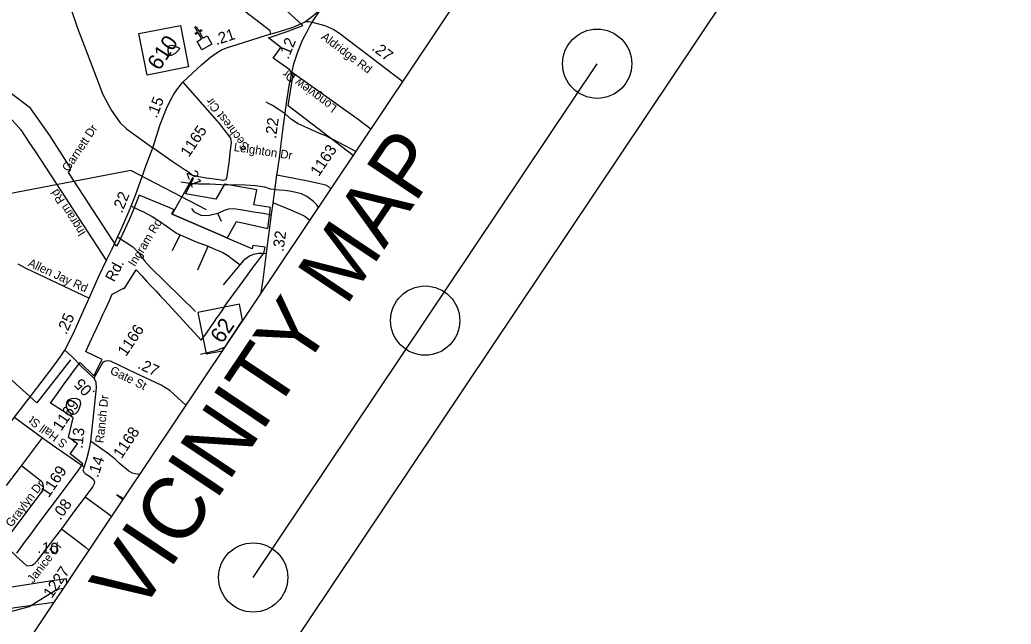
# Model space of a CAD drawing. Extents: x 1715610 to 1720914, y 798298 to 802505.
# Drawn here: x 1716054.7 to 1716295.1, y 799408.1 to 799554.8 of the extents above; entities that cross this region are included whole.
import ezdxf

# ---------------------------------------------------------------- set-up
doc = ezdxf.new("R2010")
doc.units = 0
doc.layers.add('Default', color=7, linetype='Continuous')
doc.layers.add('Prop DSN Text', color=7, linetype='Continuous')

msp = doc.modelspace()

# ---------------------------------------------------------------- linework, layer by layer
at = {"layer": 'Default'}
for p, q in [((1716103.59, 799505.81), (1716102.74, 799507.81)), ((1716091.71, 799498.76), (1716093.58, 799502.6)), ((1716097.85, 799494.11), (1716100.39, 799499.82)), ((1716104.05, 799490.45), (1716108.09, 799495.35)), ((1716103.82, 799474.49), (1716108.72, 799481.82)), ((1716053.45, 799458.31), (1716060.2, 799453.38)), ((1716055.08, 799446.56), (1716060.2, 799453.38)), ((1716051.49, 799441.8), (1716055.08, 799446.56))]:
    msp.add_line(p, q, dxfattribs=at)
for points in [[(1716135.5, 799521.82), (1716119.76, 799533.88), (1716120.92, 799540.98), (1716120.2, 799542.66), (1716116.17, 799545.47), (1716118, 799548.07), (1716114.99, 799550.42), (1716119.52, 799551.92), (1716123.32, 799553.42), (1716119.54, 799556.9), (1716117.06, 799558.69), (1716109.93, 799563.38), (1716087.19, 799580.88), (1716088.88, 799582.87), (1716060.14, 799604.73), (1716058.21, 799606.69), (1716067.68, 799613.64), (1716103.5, 799614.09), (1716121.16, 799634.15)], [(1716135.5, 799521.82), (1716119.76, 799533.88), (1716120.92, 799540.98), (1716120.2, 799542.66), (1716116.17, 799545.47), (1716118, 799548.07), (1716114.99, 799550.42), (1716119.52, 799551.92), (1716123.32, 799553.42), (1716119.54, 799556.9), (1716117.06, 799558.69), (1716109.93, 799563.38), (1716087.19, 799580.88), (1716088.88, 799582.87), (1716060.14, 799604.73), (1716058.21, 799606.69), (1716067.68, 799613.64), (1716103.5, 799614.09), (1716121.16, 799634.15)], [(1716125.61, 799554.2), (1716127.74, 799557.46), (1716130.02, 799560.94), (1716133.76, 799566.61), (1716135.23, 799568.99), (1716137.96, 799572.93), (1716140.85, 799577.4), (1716143.14, 799580.98), (1716145.26, 799584.22), (1716147.25, 799587.27), (1716150.73, 799592.47), (1716152.2, 799594.66), (1716154.43, 799597.46)], [(1716054.67, 799586.59), (1716055.43, 799581.78), (1716055.76, 799579.54), (1716056.36, 799577.31), (1716056.94, 799575.95), (1716057.52, 799575.11), (1716058.34, 799573.98), (1716060.42, 799571.98), (1716062.05, 799570.57), (1716062.97, 799569.32), (1716064.06, 799567.64), (1716064.82, 799565.56), (1716066.06, 799561), (1716067.06, 799557.48), (1716068.7, 799552.78), (1716071.13, 799546.44), (1716074.79, 799536.65), (1716076.89, 799532.76), (1716079.06, 799529.74), (1716080.59, 799528.32), (1716086.92, 799523.74)], [(1716115.47, 799551.44), (1716115.41, 799552.14), (1716105.72, 799559.54)], [(1716123.74, 799554.22), (1716125.66, 799555.67), (1716126.78, 799556.64), (1716127.74, 799557.46)], [(1716094.25, 799539.65), (1716098.86, 799543.96), (1716100.93, 799545.68), (1716102.59, 799546.87), (1716103.63, 799547.45), (1716105.04, 799548.03), (1716107.4, 799548.81), (1716114.5, 799551.03), (1716117.71, 799551.97), (1716120.96, 799552.99), (1716123.74, 799554.22), (1716124, 799554.33), (1716124.27, 799554.37), (1716124.77, 799554.39), (1716125.61, 799554.2)], [(1716117.04, 799517.05), (1716117.63, 799521.18), (1716117.97, 799524.04), (1716118.47, 799527.9), (1716119.37, 799534.56), (1716120.01, 799538.72), (1716120.71, 799542.27), (1716121.17, 799544.13), (1716122.1, 799547.03), (1716123.1, 799549.47), (1716123.68, 799550.68), (1716124.36, 799551.95), (1716124.94, 799553.08), (1716125.61, 799554.2)], [(1716125.61, 799554.2), (1716128.67, 799553.38), (1716130.84, 799552.45), (1716132.23, 799551.51), (1716134.04, 799550.15), (1716139.01, 799546.36), (1716147.56, 799539.84)], [(1716091, 799548.54), (1716091.62, 799548.59), (1716092.54, 799548.32), (1716093.43, 799547.93), (1716093.23, 799547.49), (1716092.41, 799546.67), (1716091.92, 799546.33), (1716091.39, 799546.11), (1716090.9, 799546.08), (1716090.73, 799546.29), (1716090.74, 799546.92), (1716090.66, 799547.66), (1716091, 799548.54)], [(1716091, 799548.54), (1716091.62, 799548.59), (1716092.54, 799548.32), (1716093.43, 799547.93), (1716093.23, 799547.49), (1716092.41, 799546.67), (1716091.92, 799546.33), (1716091.39, 799546.11), (1716090.9, 799546.08), (1716090.73, 799546.29), (1716090.66, 799547.66), (1716091, 799548.54)], [(1716120.73, 799542.1), (1716136.76, 799530.64), (1716139.85, 799528.32)], [(1716091.62, 799507.59), (1716091.52, 799507.63), (1716091.53, 799507.66), (1716092.11, 799508.7), (1716091.11, 799509.12), (1716083.67, 799512.22), (1716082.85, 799510.24), (1716082.07, 799508.36), (1716081.19, 799506.26), (1716079.61, 799502.79), (1716078.66, 799500.69), (1716078.11, 799499.86), (1716077.27, 799501.25), (1716066.5, 799517.71), (1716066.94, 799518.47), (1716066.86, 799519.04), (1716066.68, 799519.33), (1716061.96, 799526.72), (1716057.25, 799533.34), (1716050.04, 799538.83)], [(1716091.62, 799507.59), (1716091.52, 799507.63), (1716091.53, 799507.66), (1716092.11, 799508.7), (1716091.11, 799509.12), (1716083.67, 799512.22), (1716082.85, 799510.24), (1716082.07, 799508.36), (1716081.19, 799506.26), (1716079.61, 799502.79), (1716078.66, 799500.69), (1716078.11, 799499.86), (1716077.27, 799501.25), (1716066.5, 799517.71), (1716066.94, 799518.47), (1716066.86, 799519.04), (1716066.68, 799519.33), (1716061.96, 799526.72), (1716057.25, 799533.34), (1716050.04, 799538.83)], [(1716086.92, 799523.74), (1716088.76, 799529.38), (1716090.46, 799533.63), (1716091.61, 799535.97), (1716092.07, 799536.71), (1716093.03, 799538.14), (1716094.25, 799539.65)], [(1716094.25, 799539.65), (1716099.02, 799534.22), (1716102.52, 799530.19), (1716102.78, 799529.9), (1716105.82, 799526.08), (1716105.95, 799524.94), (1716105.64, 799522.56), (1716105.57, 799521.51), (1716105.36, 799520.09)], [(1716136.17, 799522.83), (1716133.56, 799524.21), (1716130.37, 799525.86), (1716128.91, 799526.59), (1716127.36, 799527.18), (1716125.07, 799528.22), (1716122.22, 799529.53), (1716120.62, 799530.57), (1716119.01, 799531.99), (1716117.08, 799533.25), (1716115.94, 799533.98), (1716114.97, 799534.48), (1716114.41, 799534.76)], [(1716051.41, 799531.58), (1716051.64, 799531.43), (1716052.86, 799530.43), (1716053.76, 799529.45), (1716054.94, 799528.1), (1716056.87, 799525.11), (1716058.48, 799522.74), (1716064.58, 799513.45), (1716075.73, 799496.25)], [(1716065.57, 799474.64), (1716067.02, 799477.41), (1716067.99, 799479.43), (1716070.31, 799484.58), (1716071.48, 799487.2), (1716073.97, 799492.71), (1716075.75, 799496.46), (1716077.08, 799499.19), (1716078.38, 799502.06), (1716079.49, 799504.48), (1716081.52, 799509.15), (1716082.76, 799512.24), (1716084.27, 799516.53), (1716085.33, 799519.48), (1716086.92, 799523.74)], [(1716105.36, 799520.09), (1716104.85, 799516.32), (1716104.62, 799515.91), (1716104.08, 799515.8), (1716102.51, 799516), (1716099.99, 799516.36), (1716098.09, 799516.71), (1716096.71, 799517.03), (1716096.17, 799517.35), (1716095.64, 799517.75), (1716095.18, 799518.03), (1716094.8, 799518.27), (1716091.84, 799520.25), (1716086.92, 799523.74)], [(1716099.95, 799508.66), (1716081.61, 799518.23), (1716051.68, 799512.5)], [(1716094.87, 799512.57), (1716096.85, 799516.27), (1716096.54, 799516.41), (1716094.2, 799512.22), (1716093.02, 799510.11), (1716091.62, 799507.59)], [(1716094.87, 799512.57), (1716096.85, 799516.27), (1716096.54, 799516.41), (1716094.2, 799512.22), (1716093.02, 799510.11), (1716091.62, 799507.59)], [(1716113.26, 799488.6), (1716113.69, 799491.66), (1716114.59, 799498.79), (1716115.76, 799507.57), (1716116.14, 799510.32), (1716117.04, 799517.05)], [(1716130.13, 799513.8), (1716129.62, 799514.26), (1716128.88, 799514.66), (1716127.49, 799514.98), (1716124.92, 799515.5), (1716121.22, 799516.27), (1716117.04, 799517.05)], [(1716127.09, 799509.26), (1716126.71, 799509.86), (1716125.93, 799510.66), (1716124.32, 799511.92), (1716122.97, 799512.57), (1716120.55, 799513.12), (1716118.98, 799513.36), (1716117.55, 799513.43), (1716115.47, 799513.7), (1716114.13, 799514.13), (1716111.82, 799514.45), (1716109.31, 799514.64), (1716106.89, 799514.71), (1716104.86, 799514.67), (1716100.78, 799514.87), (1716099.02, 799514.92), (1716098.05, 799514.89), (1716096.63, 799514.97), (1716095.9, 799515.05), (1716094.8, 799515.22), (1716093.76, 799515.4)], [(1716104.98, 799501.83), (1716107.23, 799505.8), (1716114.81, 799504.13), (1716115.45, 799509.27), (1716111.48, 799509.9), (1716112.15, 799513.55), (1716104.34, 799514.93), (1716102.19, 799511.29), (1716094.87, 799512.57)], [(1716104.98, 799501.83), (1716107.23, 799505.8), (1716114.81, 799504.13), (1716115.45, 799509.27), (1716111.48, 799509.9), (1716112.15, 799513.55), (1716104.34, 799514.93), (1716102.19, 799511.29), (1716094.87, 799512.57)], [(1716081.77, 799509.59), (1716083.52, 799508.68), (1716084.71, 799508.15), (1716085.76, 799507.64), (1716086.82, 799507.04), (1716088.78, 799505.75), (1716091.57, 799503.81), (1716092.69, 799503.03), (1716093.58, 799502.6)], [(1716116.18, 799510.36), (1716120.57, 799508.57), (1716123.64, 799507.19), (1716124.13, 799506.86), (1716125, 799506.14)], [(1716091.62, 799507.59), (1716095.02, 799506.12), (1716100.27, 799503.86), (1716103.99, 799502.26), (1716104.88, 799501.88), (1716104.98, 799501.83)], [(1716091.62, 799507.59), (1716095.02, 799506.12), (1716100.27, 799503.86), (1716103.99, 799502.26), (1716104.88, 799501.88), (1716104.98, 799501.83)], [(1716104.98, 799501.83), (1716104.88, 799501.88), (1716103.99, 799502.26), (1716100.27, 799503.86), (1716095.02, 799506.12), (1716091.62, 799507.59)], [(1716104.98, 799501.83), (1716104.88, 799501.88), (1716103.99, 799502.26), (1716100.27, 799503.86), (1716095.02, 799506.12), (1716091.62, 799507.59)], [(1716102.74, 799507.81), (1716100.34, 799507.2), (1716098.7, 799507.31), (1716097.06, 799508.11), (1716096.42, 799508.99)], [(1716115.8, 799507.39), (1716114.63, 799507.62), (1716113.23, 799507.84), (1716111.45, 799508.13), (1716110.03, 799508.37), (1716108.69, 799508.6), (1716106.5, 799508.91), (1716105.3, 799508.81), (1716104.23, 799508.53), (1716102.74, 799507.81)], [(1716053.94, 799425.36), (1716055.85, 799427.91), (1716057.41, 799430.01), (1716058.68, 799431.71), (1716060.55, 799434.22), (1716062.07, 799436.26), (1716063.59, 799438.3), (1716066.9, 799442.74), (1716068.79, 799445.29), (1716069.36, 799446.07), (1716070, 799447.02), (1716066.86, 799449.44), (1716068.64, 799451.87), (1716067.75, 799452.53), (1716066.9, 799453.14), (1716066.47, 799453.46), (1716067.64, 799458.21), (1716067.31, 799458.43), (1716066.89, 799458.7), (1716064.97, 799459.95), (1716062.12, 799461.78), (1716063.59, 799463.81), (1716065.71, 799466.74), (1716066.98, 799468.48), (1716067.5, 799469.21), (1716068.76, 799470.92), (1716069.36, 799471.6), (1716072.67, 799468.39), (1716074.65, 799472.36), (1716070.76, 799474.22), (1716070.69, 799474.26), (1716071.6, 799476.24), (1716072.54, 799478.3), (1716073.9, 799481.27), (1716074.33, 799482.17), (1716074.82, 799483.25), (1716075.43, 799484.57), (1716075.92, 799485.61), (1716076.41, 799486.68), (1716077.12, 799488.2), (1716079.88, 799489.68), (1716079.99, 799489.47), (1716082.89, 799494.13), (1716084.27, 799492.64), (1716085.43, 799491.38), (1716086.62, 799490.09), (1716087.72, 799488.9), (1716088.81, 799487.72), (1716089.82, 799486.63), (1716098.7, 799477.01), (1716099.52, 799478.17), (1716099.94, 799478.77), (1716101.88, 799481.53), (1716102.51, 799482.43), (1716102.94, 799483.05), (1716103.98, 799484.56), (1716104.59, 799485.5), (1716104.99, 799486.06), (1716107.49, 799489.5), (1716109.66, 799492.5), (1716111.27, 799494.72), (1716111.94, 799495.6), (1716112.69, 799496.57), (1716113.63, 799497.8), (1716113.9, 799498.14), (1716114.16, 799499.63), (1716111.18, 799500.01), (1716111.05, 799499.22), (1716104.98, 799501.83)], [(1716053.94, 799425.36), (1716055.85, 799427.91), (1716057.41, 799430.01), (1716058.68, 799431.71), (1716060.55, 799434.22), (1716062.07, 799436.26), (1716063.59, 799438.3), (1716066.9, 799442.74), (1716068.79, 799445.29), (1716069.36, 799446.07), (1716070, 799447.02), (1716066.86, 799449.44), (1716068.64, 799451.87), (1716067.75, 799452.53), (1716066.9, 799453.14), (1716066.47, 799453.46), (1716067.64, 799458.21), (1716067.31, 799458.43), (1716066.89, 799458.7), (1716064.97, 799459.95), (1716062.12, 799461.78), (1716063.59, 799463.81), (1716065.71, 799466.74), (1716066.98, 799468.48), (1716067.5, 799469.21), (1716068.76, 799470.92), (1716069.36, 799471.6), (1716072.67, 799468.39), (1716074.65, 799472.36), (1716070.76, 799474.22), (1716070.69, 799474.26), (1716071.6, 799476.24), (1716072.54, 799478.3), (1716073.9, 799481.27), (1716074.33, 799482.17), (1716074.82, 799483.25), (1716075.43, 799484.57), (1716075.92, 799485.61), (1716076.41, 799486.68), (1716077.12, 799488.2), (1716079.88, 799489.68), (1716079.99, 799489.47), (1716082.89, 799494.13), (1716084.27, 799492.64), (1716085.43, 799491.38), (1716086.62, 799490.09), (1716087.72, 799488.9), (1716088.81, 799487.72), (1716089.82, 799486.63), (1716098.7, 799477.01), (1716099.52, 799478.17), (1716099.94, 799478.77), (1716101.88, 799481.53), (1716102.51, 799482.43), (1716102.94, 799483.05), (1716103.98, 799484.56), (1716104.59, 799485.5), (1716104.99, 799486.06), (1716107.49, 799489.5), (1716109.66, 799492.5), (1716111.27, 799494.72), (1716111.94, 799495.6), (1716112.69, 799496.57), (1716113.63, 799497.8), (1716113.9, 799498.14), (1716114.16, 799499.63), (1716111.18, 799500.01), (1716111.05, 799499.22), (1716104.98, 799501.83)], [(1716078.4, 799502.08), (1716082.12, 799499.65), (1716083.22, 799498.58), (1716084.91, 799496.25), (1716086.29, 799494.73), (1716097.31, 799484.03)], [(1716093.58, 799502.6), (1716097.46, 799500.89), (1716100.39, 799499.82)], [(1716100.39, 799499.82), (1716101.62, 799499.31), (1716102.76, 799498.82), (1716103.89, 799498.34), (1716105.14, 799497.61), (1716106.21, 799496.81), (1716108.09, 799495.35)], [(1716108.09, 799495.35), (1716109, 799496.4), (1716109.3, 799496.68), (1716109.53, 799496.89), (1716109.85, 799497.12), (1716110.19, 799497.35), (1716110.54, 799497.55), (1716111, 799497.76), (1716111.39, 799497.89), (1716111.78, 799498.01), (1716112.17, 799498.1), (1716112.68, 799498.16), (1716113.08, 799498.18), (1716113.49, 799498.17), (1716114.6, 799498.04)], [(1716054.21, 799495.53), (1716056.16, 799494.52), (1716071.51, 799487.21)], [(1716108.72, 799481.82), (1716107.95, 799485.75), (1716097.9, 799483.76), (1716099.89, 799473.71), (1716103.82, 799474.49)], [(1716023.72, 799419.39), (1716026.89, 799423.57), (1716029.74, 799427.26), (1716032.22, 799430.44), (1716036.41, 799435.99), (1716038.67, 799439.03), (1716041.25, 799442.43), (1716044.69, 799447.05), (1716047.5, 799450.64), (1716049.59, 799453.33), (1716053.37, 799458.34), (1716057.77, 799464.03), (1716060.13, 799467.06), (1716062.42, 799470.15), (1716064.65, 799473.19), (1716065.57, 799474.64)], [(1716065.57, 799474.64), (1716066.3, 799473.94), (1716067.48, 799472.92), (1716069.84, 799470.46), (1716072.65, 799467.8)], [(1716104.33, 799475.26), (1716104.1, 799475.14), (1716102.26, 799474.45), (1716098.52, 799473.53)], [(1716066.98, 799472.26), (1716058.84, 799461.87), (1716047.55, 799471.96)], [(1716094.96, 799461.25), (1716091.08, 799464.81), (1716088.93, 799466.15), (1716086.41, 799467.31), (1716082.76, 799469.04), (1716076.7, 799471.93), (1716076.03, 799472.04), (1716075.25, 799471.88), (1716074.75, 799471.54), (1716074.36, 799470.85), (1716072.65, 799467.8)], [(1716072.65, 799467.8), (1716072.84, 799467.58), (1716073.15, 799466.82), (1716073.22, 799465.5), (1716072.65, 799460.09), (1716071.87, 799452.54)], [(1716069.28, 799462.51), (1716068.34, 799462.9), (1716067.22, 799462.82), (1716066.48, 799462.58), (1716066.07, 799462.13), (1716065.93, 799461.38), (1716066.01, 799460.58), (1716066.57, 799459.63), (1716067.27, 799459.1), (1716067.71, 799459.06), (1716068.24, 799459.22), (1716068.95, 799459.95), (1716069.25, 799460.85), (1716069.45, 799461.61), (1716069.43, 799462.05), (1716069.28, 799462.51)], [(1716069.28, 799462.51), (1716068.34, 799462.9), (1716067.22, 799462.82), (1716066.48, 799462.58), (1716066.07, 799462.13), (1716065.93, 799461.38), (1716066.01, 799460.58), (1716066.57, 799459.63), (1716067.27, 799459.1), (1716067.71, 799459.06), (1716068.24, 799459.22), (1716068.95, 799459.95), (1716069.25, 799460.85), (1716069.45, 799461.61), (1716069.43, 799462.05), (1716069.28, 799462.51)], [(1716060.2, 799453.38), (1716063.26, 799451.19), (1716070.26, 799446.33)], [(1716071.87, 799452.54), (1716071.64, 799451.6), (1716071.31, 799450.04), (1716070.87, 799448.17), (1716070.18, 799446.05), (1716070.01, 799445.61), (1716070.16, 799445.2), (1716070.25, 799445.02), (1716070.57, 799444.71), (1716071.84, 799443.89), (1716072.48, 799443.32), (1716072.76, 799442.78), (1716072.72, 799442.2), (1716072.36, 799441.56), (1716070.55, 799439.01)], [(1716083.73, 799444.48), (1716082.78, 799444.57), (1716081.98, 799444.79), (1716081.12, 799445.22), (1716078.82, 799447.17), (1716077.81, 799448.2), (1716075.92, 799449.65), (1716071.87, 799452.54)], [(1716050.64, 799427.74), (1716060.23, 799440.56), (1716060.4, 799441.07), (1716060.44, 799441.46), (1716060.38, 799441.99), (1716060.15, 799442.47), (1716059.91, 799442.78), (1716055.08, 799446.56)], [(1716079.8, 799438.61), (1716078.24, 799439.47), (1716079.65, 799438.38)], [(1716079.8, 799438.61), (1716078.24, 799439.47), (1716079.65, 799438.38)], [(1716070.55, 799439.01), (1716067.94, 799435.66), (1716064.79, 799431.22)], [(1716070.55, 799439.01), (1716075.64, 799435.33), (1716076.95, 799434.35)], [(1716064.79, 799431.22), (1716063.08, 799429.08), (1716060.17, 799425.3), (1716058.82, 799423.41), (1716058.15, 799422.7), (1716057.72, 799422.33), (1716057.45, 799422.27)], [(1716064.79, 799431.22), (1716070.52, 799426.9), (1716071.43, 799426.1)], [(1716066.09, 799418.12), (1716066.04, 799419.13), (1716061.96, 799418.53), (1716050.15, 799416.73), (1716045.18, 799421.02), (1716036.77, 799428.3), (1716034, 799424.6), (1716029.92, 799419.28), (1716027.99, 799416.77)], [(1716066.09, 799418.12), (1716066.04, 799419.13), (1716061.96, 799418.53), (1716050.15, 799416.73), (1716045.18, 799421.02), (1716036.77, 799428.3), (1716034, 799424.6), (1716029.92, 799419.28), (1716027.99, 799416.77)], [(1716050.64, 799427.74), (1716053.64, 799424.8), (1716056.38, 799422.25), (1716057.7, 799422.46)], [(1716062.92, 799413.39), (1716051.75, 799411.85), (1716048.28, 799412.09), (1716046.02, 799414.13), (1716039.22, 799419.49)], [(1716065.19, 799416.77), (1716063.71, 799416.54), (1716056.96, 799412.37), (1716050.23, 799410.59), (1716029.64, 799389.75)]]:
    msp.add_lwpolyline(points, dxfattribs=at)
for points in [[(1716085.57, 799541.38), (1716083.58, 799551.43), (1716093.62, 799553.42), (1716095.61, 799543.37)], [(1716097.68, 799549.53), (1716098.76, 799550.13), (1716097.96, 799551.58), (1716097.35, 799551.24), (1716097.18, 799551.54), (1716097.79, 799551.88), (1716097.16, 799553.02), (1716097.46, 799553.19), (1716098.1, 799552.05), (1716098.71, 799552.39), (1716098.87, 799552.08), (1716098.26, 799551.74), (1716099.07, 799550.29), (1716100.16, 799550.9), (1716101.28, 799548.87), (1716098.8, 799547.5)]]:
    msp.add_lwpolyline(points, close=True, dxfattribs=at)
at = {"layer": 'Prop DSN Text'}
msp.add_line((1716111.28, 799419.46), (1716194.72, 799544.12), dxfattribs=at)
for points in [[(1715972.32, 799278.02), (1716250.51, 799693.66), (1715888.23, 799936.14), (1715610.03, 799520.5)], [(1715972.32, 799278.02), (1716250.51, 799693.66), (1716295.13, 799663.8), (1716016.93, 799248.16)]]:
    msp.add_lwpolyline(points, close=True, dxfattribs=at)
for centre in [(1716194.72, 799544.12), (1716153, 799481.79), (1716111.28, 799419.46)]:
    msp.add_circle(centre, 8.4, dxfattribs=at)

# ---------------------------------------------------------------- texts
at = {"layer": 'Default'}
for s, height, rotation, p in [('.21', 2.719, 18.2368, (1716102.37, 799548.58)), ('610', 3.806, 56.2051, (1716088.51, 799542.27)), ('.12', 2.719, 67.5952, (1716119.81, 799545.06)), ('Aldridge Rd', 2.0663, 323.0638, (1716127.59, 799550.29)), ('.27', 2.719, 322.5492, (1716139.87, 799547.6)), ('Longview Dr', 2.0663, 143.682, (1716131.75, 799533.73)), ('.15', 2.719, 68.2798, (1716087.85, 799530.75)), ('Sechrest Cir', 2.0663, 126.9771, (1716110.42, 799523.98)), ('.22', 2.719, 82.2733, (1716116.82, 799525.84)), ('Garnett Dr', 2.066, 56.2051, (1716066.49, 799517.77)), ('1165', 2.719, 56.2051, (1716095.68, 799521.26)), ('Leighton Dr', 2.0663, 351.4609, (1716106.49, 799522.96)), ('1163', 2.719, 56.2051, (1716127.2, 799516.6)), ('.21', 2.719, 290.5699, (1716094.67, 799518.61)), ('Ingram Rd', 2.066, 122.6768, (1716070.77, 799503.1)), ('.22', 2.719, 68.2476, (1716079.48, 799507.7)), ('Ingram Rd', 2.066, 58.5915, (1716082.58, 799494.73)), ('.32', 2.719, 82.4242, (1716118.65, 799498.38)), ('Allen Jay Rd', 2.0663, 335.3224, (1716056.49, 799495.08)), ('Rd.', 2.61, 62.7185, (1716077.57, 799491.01)), ('.25', 2.719, 65.7217, (1716065.95, 799478.21)), ('1166', 2.719, 56.2051, (1716080.45, 799472.95)), ('62', 3.806, 56.2051, (1716103.77, 799476.01)), ('Gate St', 2.066, 333.7816, (1716076.38, 799469.01)), ('.27', 2.719, 334.4183, (1716083.05, 799470.33)), ('.05', 2.719, 134.465, (1716073.1, 799464.4)), ('Ranch Dr', 2.066, 83.9755, (1716075, 799451.99)), ('1169', 2.719, 56.2051, (1716064.71, 799454.8)), ('S Hall St', 2.066, 143.5924, (1716066.41, 799452.35)), ('.13', 2.719, 84.079, (1716069.86, 799450.64)), ('1168', 2.719, 56.2051, (1716079.37, 799448.13)), ('.14', 2.719, 71.9232, (1716073.65, 799443.55)), ('1169', 2.719, 56.2051, (1716061.7, 799438.66)), ('Graylyn Dr', 2.066, 52.5196, (1716052.67, 799431.49)), ('.08', 2.719, 54.6538, (1716064.52, 799433.19)), ('Janice Dr', 2.066, 51.9874, (1716057.9, 799417.92)), ('.10', 2.719, 356.2816, (1716058.91, 799425.42)), ('1227', 2.719, 56.2051, (1716062.43, 799414.24))]:
    msp.add_text(s, height=height, rotation=rotation, dxfattribs=at).set_placement(p)
at = {"layer": 'Prop DSN Text'}
msp.add_text('VICINITY MAP', height=15, rotation=56.2051, dxfattribs=at).set_placement((1716083.55, 799410.02))

doc.saveas('drawing.dxf')
